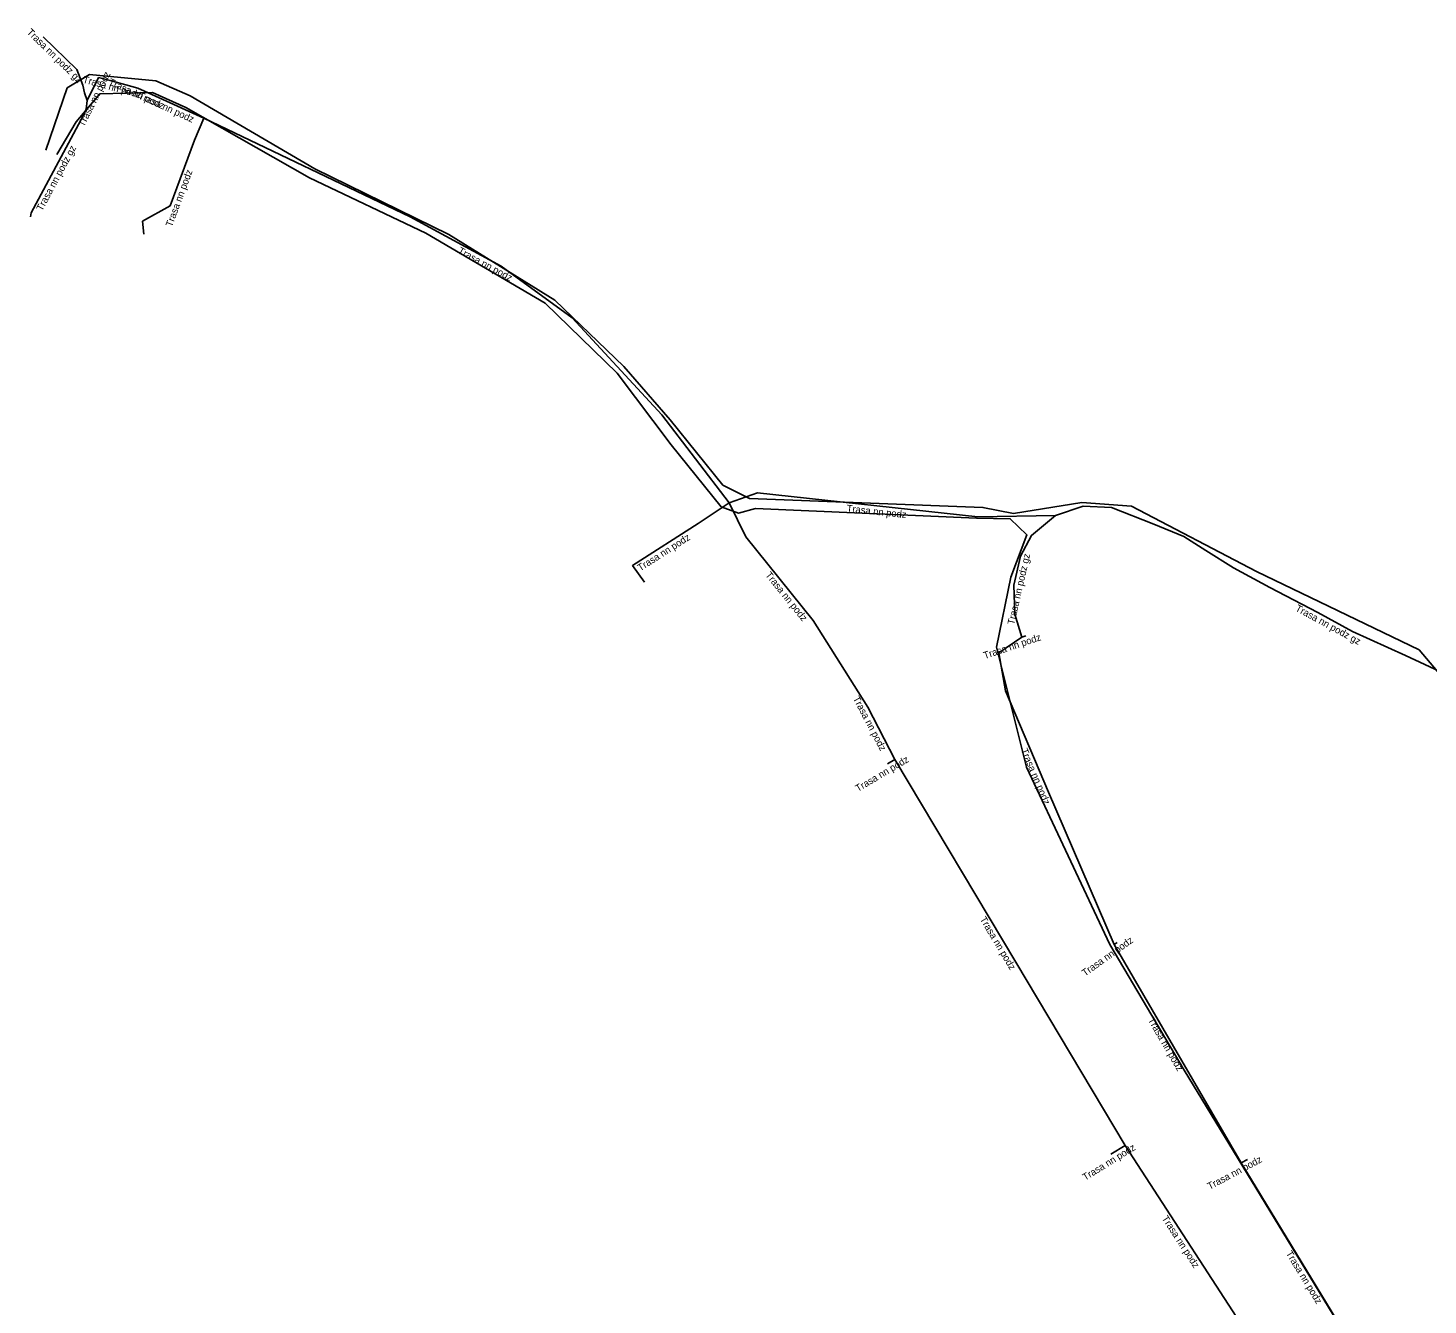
# Model space of a CAD drawing. Extents: x -748073 to -746986, y -1069233 to -1068700.
# Drawn here: x -747651.1 to -747551.4, y -1068826.2 to -1068735.3 of the extents above; entities that cross this region are included whole.
import ezdxf

# ---------------------------------------------------------------- set-up
doc = ezdxf.new("R2010")
doc.units = 0
for name, color, linetype in [('Popiskový text - Ostatní atributy Trasy', 7, 'Continuous'), ('Spojnice NN', 7, 'Continuous'), ('Spojnice VN', 7, 'Continuous')]:
    doc.layers.add(name, color=color, linetype=linetype)

msp = doc.modelspace()

# ---------------------------------------------------------------- linework, layer by layer
at = {"layer": 'Spojnice NN'}
for points in [[(-747646.869, -1068740.482), (-747647.043, -1068739.931), (-747647.184, -1068739.389), (-747647.599, -1068738.262), (-747649.99, -1068735.93)], [(-747645.233, -1068739.055), (-747646.05, -1068738.84), (-747646.869, -1068740.482)], [(-747642.794, -1068739.802), (-747643.26, -1068739.59), (-747645.233, -1068739.055)], [(-747650.907, -1068748.76), (-747650.851, -1068748.463), (-747647.124, -1068741.525), (-747646.927, -1068741.091), (-747646.869, -1068740.482)], [(-747641.729, -1068740.287), (-747642.794, -1068739.802)], [(-747638.56, -1068741.73), (-747641.729, -1068740.287)], [(-747638.56, -1068741.73), (-747639.23, -1068743.3), (-747640.95, -1068747.96), (-747642.93, -1068749.07), (-747642.84, -1068750)], [(-747601.16, -1068769.12), (-747605.97, -1068762.85), (-747612.35, -1068755.95), (-747617.4, -1068752.27), (-747623.87, -1068748.76), (-747638.56, -1068741.73)], [(-747577.94, -1068770.02), (-747583.46, -1068770.11), (-747599.16, -1068768.4), (-747601.16, -1068769.12)], [(-747601.16, -1068769.12), (-747603.37, -1068770.59), (-747608.04, -1068773.58), (-747607.2, -1068774.75)], [(-747601.16, -1068769.12), (-747599.99, -1068771.53), (-747595.2, -1068777.48), (-747591.31, -1068783.67)], [(-747536.07, -1068787), (-747537.38, -1068786.46), (-747540.2, -1068785.72), (-747542.86, -1068784.75), (-747545.28, -1068783.8), (-747547.88, -1068782.59), (-747550.27, -1068781.26), (-747553.04, -1068779.99), (-747556.8, -1068778.27), (-747559.26, -1068776.93), (-747562.68, -1068775.13), (-747565.26, -1068773.73), (-747567.25, -1068772.51), (-747568.81, -1068771.52), (-747570.93, -1068770.64), (-747573.96, -1068769.45), (-747575.98, -1068769.36), (-747577.94, -1068770.02)], [(-747577.94, -1068770.02), (-747579.65, -1068771.43), (-747580.43, -1068772.9), (-747580.9, -1068774.97), (-747580.83, -1068777.05), (-747580.34, -1068778.67)], [(-747580.34, -1068778.67), (-747581.98, -1068779.8), (-747581.51, -1068782.49), (-747578.44, -1068789.71), (-747573.76, -1068800.56)], [(-747580.34, -1068778.67), (-747580.054, -1068778.574)], [(-747591.31, -1068783.67), (-747589.37, -1068787.38)], [(-747589.37, -1068787.38), (-747589.89, -1068787.69)], [(-747589.37, -1068787.38), (-747580.76, -1068801.82), (-747572.99, -1068814.86)], [(-747573.76, -1068800.56), (-747573.55, -1068800.41)], [(-747573.76, -1068800.56), (-747564.72, -1068816.09)], [(-747572.99, -1068814.86), (-747574, -1068815.486)], [(-747572.99, -1068814.86), (-747563.29, -1068829.82)], [(-747564.72, -1068816.09), (-747564.27, -1068815.85)], [(-747564.72, -1068816.09), (-747556.85, -1068829.06), (-747554.16, -1068833.77)]]:
    msp.add_lwpolyline(points, dxfattribs=at)
at = {"layer": 'Spojnice VN'}
for points in [[(-747649.8, -1068744.01), (-747648.29, -1068739.58), (-747646.69, -1068738.63), (-747641.97, -1068739.08), (-747639.53, -1068740.13), (-747630.66, -1068745.33), (-747621.13, -1068750.01), (-747613.58, -1068754.68), (-747608.67, -1068759.4), (-747605.36, -1068763.21), (-747601.62, -1068767.85), (-747599.72, -1068768.81), (-747583.11, -1068769.44), (-747580.93, -1068769.87), (-747576.06, -1068769.09), (-747572.54, -1068769.36), (-747563.64, -1068774.01), (-747552.06, -1068779.58), (-747550.74, -1068781.11)], [(-747649.02, -1068744.31), (-747647.65, -1068741.98), (-747645.97, -1068740.01), (-747642.22, -1068739.9), (-747639.84, -1068740.97), (-747631.03, -1068745.99), (-747622.75, -1068749.92), (-747614.27, -1068754.9), (-747609.14, -1068759.88), (-747605.29, -1068764.98), (-747601.73, -1068769.41), (-747600.5, -1068769.85), (-747599.3, -1068769.52), (-747583.56, -1068770.21), (-747581.16, -1068770.25), (-747579.97, -1068771.38), (-747581.11, -1068774.41), (-747582.15, -1068779.38), (-747580.01, -1068787.92), (-747574.07, -1068800.56), (-747568.78, -1068809.51), (-747553.42, -1068834.74)]]:
    msp.add_lwpolyline(points, dxfattribs=at)

# ---------------------------------------------------------------- texts
at = {"layer": 'Popiskový text - Ostatní atributy Trasy'}
for s, rotation, p in [('Trasa nn podz gz', 315.71571, (-747651.199, -1068735.659)), ('Trasa nn podz', 63.49081, (-747647.094, -1068742.39)), ('Trasa nn podz', 344.83029, (-747647.207, -1068739.194)), ('Trasa nn podz', 335.51831, (-747645.395, -1068739.332)), ('Trasa nn podz', 335.51902, (-747643.278, -1068740.296)), ('Trasa nn podz gz', 61.75591, (-747650.071, -1068748.385)), ('Trasa nn podz', 69.74096, (-747640.829, -1068749.51)), ('Trasa nn podz', 331.52, (-747620.52, -1068751.317)), ('Trasa nn podz', 353.78401, (-747592.822, -1068769.744)), ('Trasa nn podz', 32.62969, (-747607.494, -1068774.003)), ('Trasa nn podz gz', 77.2077, (-747580.881, -1068777.823)), ('Trasa nn podz', 308.83553, (-747598.623, -1068774.265)), ('Trasa nn podz gz', 331.42219, (-747560.915, -1068776.769)), ('Trasa nn podz', 18.55507, (-747582.974, -1068780.24)), ('Trasa nn podz', 297.60557, (-747592.374, -1068783.037)), ('Trasa nn podz', 30.80145, (-747592.001, -1068789.706)), ('Trasa nn podz', 293.03557, (-747580.417, -1068786.722)), ('Trasa nn podz', 300.80595, (-747583.349, -1068798.749)), ('Trasa nn podz', 35.53768, (-747575.839, -1068802.843)), ('Trasa nn podz', 300.20365, (-747571.386, -1068805.931)), ('Trasa nn podz', 31.79072, (-747575.828, -1068817.384)), ('Trasa nn podz', 28.07249, (-747566.967, -1068818.025)), ('Trasa nn podz', 302.9592, (-747570.398, -1068820.053)), ('Trasa nn podz', 301.24874, (-747561.567, -1068822.54))]:
    msp.add_text(s, height=0.5, rotation=rotation, dxfattribs=at).set_placement(p)

doc.saveas('drawing.dxf')
